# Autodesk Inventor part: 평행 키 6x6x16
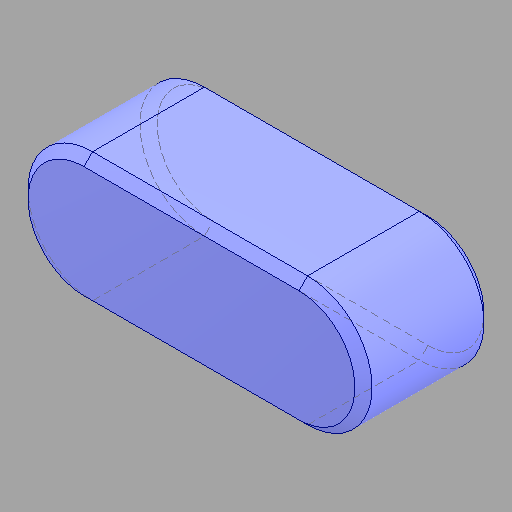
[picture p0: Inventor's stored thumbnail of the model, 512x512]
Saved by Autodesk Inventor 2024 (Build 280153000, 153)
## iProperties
Created: 2025-11
Part Number: 평행 키 6x6x16
Material: 강철, 연강
Description: 키 및 해당 키홈
Document SubType Name: Modeling
Designer: Edu09
Density: 7.85 g/cm^3
Appearance: 기본값
Author: jhkim
Sending System: Autodesk Inventor 2026
Preprocessor: ST-DEVELOPER v20.1
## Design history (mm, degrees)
feature "Solid1"
node "솔리드1"
